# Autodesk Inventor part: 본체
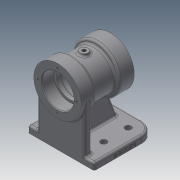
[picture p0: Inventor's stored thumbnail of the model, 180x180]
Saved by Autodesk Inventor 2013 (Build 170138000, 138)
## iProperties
Created: 2020-06
Part Number: 본체
Material: 일반
Document SubType Name: Modeling
Designer: 19
Density: 1 g/cm^3
Mass: 268.673 g
Surface Area: 641.499 cm^2
Volume: 268.673 cm^3
Author: 19
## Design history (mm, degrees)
sketch "스케치2"
  geometry: C1 r 35 at (0, 0); 1 further point
  constraints: 1 centre point, 1 coincident
  dimensions: "d8" = 70 diameter of C1
extrude "돌출1" new body sketch "스케치2" distance "d10" = 22; taper "d11" = 0 deg
sketch "스케치3"
  geometry: C1 r 35 at (0, 0) reference; C2 r 29 at (0, 0)
  constraints: 1 centre point, 1 coincident
  dimensions: "d12" = 29 radius of C2
extrude "돌출2" join sketch "스케치3" distance "d13" = 34; taper "d14" = 0 deg
sketch "스케치4"
  geometry: C1 r 29 at (0, 0) reference; C2 r 35 at (0, 0)
  constraints: 1 centre point, 1 coincident
  dimensions: "d15" = 35 radius of C2
extrude "돌출3" join sketch "스케치4" distance "d16" = 22; taper "d17" = 0 deg
sketch "스케치5"
  geometry: C1 r 35 at (0, 0) reference; C2 r 23.5 at (0, 0)
  constraints: 1 centre point, 1 coincident
  dimensions: "d18" = 47 diameter of C2
extrude "돌출4" cut sketch "스케치5" distance "d20" = 18; taper "d21" = 0 deg
sketch "스케치6"
  geometry: C1 r 23.5 at (0, 0) reference; C2 r 20 at (0, 0)
  constraints: 1 centre point, 1 coincident
  dimensions: "d22" = 20 radius of C2
extrude "돌출5" cut sketch "스케치6" distance "d23" = 6; taper "d24" = 0 deg
sketch "스케치7"
  geometry: C1 r 20 at (0, 0) reference; C2 r 23 at (0, 0)
  constraints: 1 centre point, 1 coincident
  dimensions: "d25" = 46 diameter of C2
extrude "돌출6" cut sketch "스케치7" distance "d27" = 30; taper "d28" = 0 deg
sketch "스케치8"
  geometry: C1 r 35 at (0, 0) reference; C2 r 23.5 at (0, 0)
  constraints: 1 centre point, 1 coincident
  dimensions: "d29" = 47 diameter of C2
extrude "돌출7" cut sketch "스케치8" distance "d31" = 18; taper "d32" = 0 deg
sketch "스케치9"
  geometry: C1 r 23.5 at (0, 0) reference; C2 r 20 at (0, 0)
  constraints: 1 centre point, 1 coincident
  dimensions: "d33" = 20 radius of C2
extrude "돌출8" cut sketch "스케치9" distance "d34" = 6; taper "d35" = 0 deg
node "작업 평면2"
  node "작업 평면1"
sketch "스케치10"
  geometry: L1 (14.177, 34)-(-14.177, 34) reference; L2 (-14.177, 34)-(-14.177, 56) reference; L3 (-14.177, 56)-(14.177, 56) reference; L4 (14.177, 56)-(14.177, 34) reference; L5 (-14.177, -22)-(-14.177, 0) reference; L6 (-14.177, 0)-(14.177, 0) reference; L7 (14.177, 0)-(14.177, -22) reference; L8 (14.177, -22)-(-14.177, -22) reference; C1 r 6 at (0, 17); 2 further points
  constraints: 1 centre point, 1 midpoint, 1 vertical alignment
  dimensions: "d41" = 12 diameter of C1; "d42" = 39 distance from line of L3 C1.centre
extrude "돌출9" join sketch "스케치10" stored distance "d43" = 3; taper "d44" = 0 deg
sketch "스케치11"
  geometry: C1 r 6 at (0, 0) reference; 1 further point
hole "구멍1" sketch "스케치11" at (0, 0) diameter "d45" = 5.188; stored, may be unused: countersink angle "d49" = 90 deg, drill point angle "d51" = 118 deg; dims "d46" = 30, "d47" = 4, "d48" = 2, "d50" = 8
node "작업 평면3"
sketch "스케치12"
  geometry: L1 (49, 73)-(-49, 73); L2 (-49, 73)-(-49, -17); L3 (-49, -17)-(49, -17); L4 (49, -17)-(49, 73); L5 (35, 78)-(-35, 78) reference; L6 (-35, 0)-(35, 0) reference; 5 further points
  constraints: 8 end point, 4 midpoint, 2 parallel, 2 vertical alignment, 1 horizontal, 1 perpendicular
  dimensions: "d53" = 5 distance between parallel lines of L1 L5; "d54" = 90 distance of L3.end L1.start; "d55" = 98 distance of L2.end L3.end
extrude "돌출10" join sketch "스케치12" distance "d56" = 10; taper "d57" = 0 deg
sketch "스케치13"
  geometry: L1 (-49, -73)-(49, -73) reference; L2 (-35, -63)-(35, -63); L3 (35, -63)-(35, -73); L4 (35, -73)-(-35, -73); L5 (-35, -73)-(-35, -63); 3 further points
  constraints: 8 end point, 3 midpoint, 2 parallel, 1 horizontal, 1 perpendicular, 1 vertical alignment
  dimensions: "d58" = 10 distance of L2.end L3.end; "d60" = 70 distance of L2.start L2.end
extrude "돌출11" join sketch "스케치13" stored distance "d61" = 10; taper "d62" = 0 deg
sketch "스케치14"
  geometry: L1 (-35, -63)-(35, -63) reference; L2 (49, 17)-(-49, 17) reference; L3 (-5, 5)-(5, 5); L4 (5, 5)-(5, -63); L5 (5, -63)-(-5, -63); L6 (-5, -63)-(-5, 5); 3 further points
  constraints: 8 end point, 3 midpoint, 2 parallel, 1 horizontal, 1 perpendicular, 1 vertical alignment
  dimensions: "d63" = 12 distance between parallel lines of L3 L2; "d64" = 10 distance of L3.start L3.end
extrude "돌출12" join sketch "스케치14" stored distance "d66" = 10; taper "d67" = 0 deg
feature "면 기울기1" dims angle "d68" = 20 deg
sketch "스케치15"
  geometry: L1 (0, 28.5)-(0, 0); L2 (0, 0)-(28.5, 0); L3 (-28.5, 0)-(0, 0); L4 (0, -28.5)-(0, 0); C1 r 35 at (0, 0) reference; A1 r 28.5 centre (0, 0) between (0, 28.5) and (28.5, 0)
  constraints: 8 end point, 4 point on circle, 2 perpendicular, 1 centre point, 1 coincident, 1 collinear, 1 vertical
  dimensions: "d69" = 57 diameter of A1
hole "구멍2" sketch "스케치15" at (0, 28.5), (28.5, 0), (-28.5, 0), (0, -28.5) diameter "d71" = 3.242; stored, may be unused: countersink angle "d75" = 90 deg, drill point angle "d77" = 118 deg; dims "d72" = 10, "d73" = 4, "d74" = 2, "d76" = 12
sketch "스케치16"
  geometry: L1 (0, 0)-(0, 28.5); L2 (0, 0)-(28.5, 0); L3 (0, 0)-(0, -28.5); L4 (0, 0)-(-28.5, 0); C1 r 23.5 at (0, 0) reference; A1 r 28.5 centre (0, 0) between (0, 28.5) and (28.5, 0)
  constraints: 8 end point, 4 point on circle, 3 perpendicular, 1 centre point, 1 coincident, 1 vertical
  dimensions: "d78" = 57 diameter of A1
hole "구멍3" sketch "스케치16" at (0, 28.5), (28.5, 0), (0, -28.5), (-28.5, 0) diameter "d80" = 3.242; stored, may be unused: countersink angle "d84" = 90 deg, drill point angle "d86" = 118 deg; dims "d81" = 10, "d82" = 4, "d83" = 2, "d85" = 12
sketch "스케치18"
  geometry: L1 (0, 0)-(90, 0) reference; L2 (0, 0)-(0, 10) reference; 2 further points
  constraints: 1 other
  dimensions: "d87" = 4 distance from line of L1 point (45, 4); "d88" = 45 distance from line of point (45, 4) L2
feature "엠보싱1" sketch "스케치18" dims "d8" = 70, "d89" = 0.5, "d90" = 0
chamfer "모따기1" distance "d91" = 1; stored, may be unused: second distance "d92" = 2, angle "d93" = 45 deg
fillet "모깎기1" dims "d94" = 0.3
fillet "모깎기2" dims "d95" = 3
fillet "모깎기3" dims "d96" = 3
fillet "모깎기4" dims "d97" = 3
fillet "모깎기5" dims "d98" = 3
fillet "모깎기6" dims "d99" = 20
sketch "스케치19"
  geometry: C1 r 4.5 at (-29, -3); C2 r 4.5 at (29, -3); C3 r 4.5 at (-29, -39); C4 r 4.5 at (29, -39); A1 r 20 centre (-29, -3) between (-29, 17) and (-49, -3) reference; A2 r 20 centre (29, -3) between (49, -3) and (29, 17) reference; 1 further point
  constraints: 4 centre point, 2 concentric, 2 vertical alignment
  dimensions: "d106" = 4.5 radius of C1; "d107" = 4.5 radius of C2; "d110" = 4.5 radius of C3; "d111" = 4.5 radius of C4; "d122" = 36 distance of C2.centre C4.centre; "d123" = 36 distance of A1.centre C3.centre
extrude "돌출13" cut sketch "스케치19" stored distance "d112" = 9; taper "d113" = 0 deg
fillet "모깎기15" dims "d116" = 3
fillet "모깎기16" dims "d117" = 3
fillet "모깎기17" dims "d118" = 3
fillet "모깎기18" dims "d119" = 3
fillet "모깎기19" dims "d120" = 3
fillet "모깎기20" dims "d121" = 3
node "솔리드1"
node "절단 모서리 투영1"
other parameters: "d36" = 3
